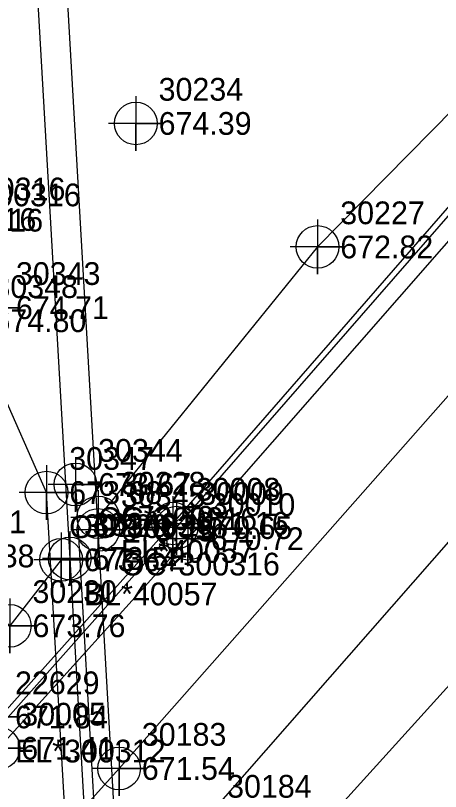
# Model space of a CAD drawing. Extents: x 1331606 to 1438728, y -485208 to 1373898.
# Drawn here: x 1378923.5 to 1378970.2, y 552509.2 to 552594.5 of the extents above; entities that cross this region are included whole.
import ezdxf

# ---------------------------------------------------------------- set-up
doc = ezdxf.new("R2010")
doc.units = 0
for name, color, linetype in [('Exist DTM Breakline', 7, 'Continuous'), ('Exist DTM Breakline Cogo Comment', 7, 'Continuous'), ('Exist DTM Breakline Cogo Elevation', 7, 'Continuous'), ('Exist DTM Breakline Cogo Number', 7, 'Continuous'), ('Exist DTM Breakline Cogo Point CELL', 7, 'Continuous'), ('Exist DTM Crownline', 7, 'Continuous'), ('Exist DTM Crownline Cogo Number', 7, 'Continuous'), ('Exist DTM Drainline', 7, 'Continuous'), ('Exist DTM Drainline Cogo Elevation', 7, 'Continuous'), ('Exist DTM Drainline Cogo Number', 7, 'Continuous'), ('Exist DTM Drainline Cogo Point CELL', 7, 'Continuous'), ('Exist DTM Regular Point CELL', 7, 'Continuous'), ('Exist DTM Regular Point Cogo Elevation', 7, 'Continuous'), ('Exist DTM Regular Point Cogo Number', 7, 'Continuous'), ('Exist Roads Curbs', 7, 'Continuous'), ('Exist Roads Curbs Cogo Elevation', 7, 'Continuous'), ('Exist Roads Curbs Cogo Number', 7, 'Continuous'), ('Exist Roads Curbs Cogo Point CELL', 7, 'Continuous'), ('Exist Roads EOP', 7, 'Continuous'), ('Exist Roads EOP Cogo Elevation', 7, 'Continuous'), ('Exist Roads EOP Cogo Number', 7, 'Continuous'), ('Exist Roads EOP Cogo Point CELL', 7, 'Continuous'), ('Exist Roads EOP Other', 7, 'Continuous'), ('Exist Roads EOP Other Cogo Comment', 7, 'Continuous'), ('Exist Roads EOP Other Cogo Elevation', 7, 'Continuous'), ('Exist Roads EOP Other Cogo Number', 7, 'Continuous'), ('Exist Roads EOP Other Cogo Point CELL', 7, 'Continuous')]:
    doc.layers.add(name, color=color, linetype=linetype)

msp = doc.modelspace()

# ---------------------------------------------------------------- linework, layer by layer
at = {"layer": 'Exist DTM Breakline'}
for points in [[(1378894.8683, 552467.2034), (1378934.875, 552511.6988000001), (1378975.1913, 552557.3482), (1379012.2256, 552601.234), (1379047.8235, 552643.3066), (1379082.4488, 552684.9015), (1379094.3392993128, 552699.1852953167)], [(1378910.6065, 552451.3821), (1378952.3237, 552500.0593), (1378989.7563, 552541.3574), (1379029.1553, 552588.5078000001), (1379065.8772, 552631.0756), (1379101.3476, 552673.4477), (1379110.1890436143, 552683.7234827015)], [(1378951.3861, 552645.2498), (1378973.7368000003, 552623.2363), (1378983.8492, 552608.8693000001), (1378981.7635000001, 552594.4797), (1378956.6937000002, 552569.0235), (1378932.5816, 552539.3052)], [(1378928.5073, 552534.6307), (1378922.8528, 552527.3836), (1378912.8515, 552535.0599), (1378897.7705, 552549.1205)]]:
    msp.add_lwpolyline(points, dxfattribs=at)
at = {"layer": 'Exist DTM Breakline Cogo Point CELL'}
for points in [[(1378956.6937000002, 552572.0235), (1378956.6937000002, 552566.0235), (1378956.6937000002, 552569.0235), (1378959.6937000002, 552569.0235), (1378953.6937000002, 552569.0235)], [(1378932.5816, 552542.3052), (1378932.5816, 552536.3052), (1378932.5816, 552539.3052), (1378935.5816, 552539.3052), (1378929.5816, 552539.3052)], [(1378928.5073, 552537.6307), (1378928.5073, 552531.6307), (1378928.5073, 552534.6307), (1378931.5073, 552534.6307), (1378925.5073, 552534.6307)], [(1378922.8528, 552530.3836), (1378922.8528, 552524.3836), (1378922.8528, 552527.3836), (1378925.8528, 552527.3836), (1378919.8528, 552527.3836)], [(1378934.875, 552514.6988000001), (1378934.875, 552508.6988000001), (1378934.875, 552511.6988000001), (1378937.875, 552511.6988000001), (1378931.875, 552511.6988000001)]]:
    msp.add_lwpolyline(points, dxfattribs=at)
for centre in [(1378956.6937000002, 552569.0235), (1378932.5816, 552539.3052000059), (1378928.5073, 552534.6307000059), (1378922.8528, 552527.3836), (1378934.875, 552511.6988000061)]:
    msp.add_circle(centre, 2.344041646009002, dxfattribs=at)
at = {"layer": 'Exist DTM Crownline'}
msp.add_lwpolyline([(1378902.6769, 552459.2259), (1378944.252, 552505.99), (1378983.1059, 552550.2917), (1379020.4991, 552594.1175), (1379056.3507, 552636.748), (1379092.2886, 552679.84), (1379102.2671428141, 552691.4514903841)], dxfattribs=at)
at = {"layer": 'Exist DTM Drainline'}
msp.add_lwpolyline([(1378909.8591, 552502.9524), (1378941.1956, 552538.1749), (1378973.607, 552575.312), (1378987.747, 552591.8377)], dxfattribs=at)
at = {"layer": 'Exist DTM Drainline Cogo Point CELL'}
msp.add_lwpolyline([(1378941.1956, 552541.1749), (1378941.1956, 552535.1749), (1378941.1956, 552538.1749), (1378944.1956, 552538.1749), (1378938.1956, 552538.1749)], dxfattribs=at)
msp.add_circle((1378941.1956, 552538.1749000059), 2.344041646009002, dxfattribs=at)
at = {"layer": 'Exist DTM Regular Point CELL'}
msp.add_lwpolyline([(1378936.7217, 552585.6003), (1378936.7217, 552579.6003), (1378936.7217, 552582.6003), (1378939.7217, 552582.6003), (1378933.7217, 552582.6003)], dxfattribs=at)
msp.add_circle((1378936.7217, 552582.600300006), 2.344041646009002, dxfattribs=at)
at = {"layer": 'Exist Roads Curbs'}
msp.add_lwpolyline([(1378909.3072, 552503.4156), (1378940.8032, 552538.6427), (1378973.2124, 552575.8521), (1378987.2210000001, 552592.2511)], dxfattribs=at)
at = {"layer": 'Exist Roads Curbs Cogo Point CELL'}
msp.add_lwpolyline([(1378940.8032, 552541.6427), (1378940.8032, 552535.6427), (1378940.8032, 552538.6427), (1378938.0732000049, 552538.6427), (1378943.8032, 552538.6427)], dxfattribs=at)
msp.add_circle((1378940.8032, 552538.6427000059), 2.344041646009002, dxfattribs=at)
at = {"layer": 'Exist Roads EOP'}
msp.add_lwpolyline([(1378887.2676, 552475.3281), (1378921.622, 552513.9192), (1378942.4529, 552536.9515), (1378975.0316, 552574.1483), (1378989.0404, 552590.539)], dxfattribs=at)
msp.add_spline([(1378922.0202, 552447.8495), (1378948.3154, 552477.2189), (1378976.9149, 552509.0975), (1378983.8473, 552517.0012), (1379007.2744000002, 552543.9418), (1379035.5047000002, 552576.1768000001), (1379055.8822, 552599.2135), (1379082.2093, 552631.1586000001), (1379098.0889, 552650.3861)], degree=3, dxfattribs=at)
at = {"layer": 'Exist Roads EOP Cogo Point CELL'}
for points in [[(1378942.4529, 552539.9515), (1378942.4529, 552533.9515), (1378942.4529, 552536.9515), (1378945.4529, 552536.9515), (1378939.4529, 552536.9515)], [(1378921.622, 552516.9192), (1378921.622, 552510.9192), (1378921.622, 552513.9192), (1378924.622, 552513.9192), (1378918.622, 552513.9192)]]:
    msp.add_lwpolyline(points, dxfattribs=at)
for centre in [(1378942.4529, 552536.9515), (1378921.622, 552513.9192)]:
    msp.add_circle(centre, 2.344041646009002, dxfattribs=at)
at = {"layer": 'Exist Roads EOP Other'}
msp.add_line((1378926.8962, 552542.0254000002), (1378918.5576, 552560.9177000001), dxfattribs=at)
msp.add_spline([(1378930.0704, 552542.9155), (1378932.5817, 552537.9158), (1378932.5817, 552537.9158), (1378929.449, 552534.7859), (1378926.8962, 552542.0254000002)], degree=3, dxfattribs=at)
at = {"layer": 'Exist Roads EOP Other Cogo Point CELL'}
for points in [[(1378921.0309, 552565.3498), (1378921.0309, 552559.3498), (1378921.0309, 552562.3498), (1378924.0309, 552562.3498), (1378918.0309, 552562.3498)], [(1378930.0704, 552545.9155), (1378930.0704, 552539.9155), (1378930.0704, 552542.9155), (1378933.0704, 552542.9155), (1378927.0704, 552542.9155)], [(1378926.8962, 552545.0254000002), (1378926.8962, 552539.0254000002), (1378926.8962, 552542.0254000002), (1378929.8962, 552542.0254000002), (1378923.8962, 552542.0254000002)], [(1378932.5817, 552540.9158), (1378932.5817, 552534.9158), (1378932.5817, 552537.9158), (1378935.5817, 552537.9158), (1378929.5817, 552537.9158)], [(1378932.5817000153, 552540.9157999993), (1378932.5817000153, 552534.9157999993), (1378932.5817000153, 552537.9157999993), (1378935.5817000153, 552537.9157999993), (1378929.5817000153, 552537.9157999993)], [(1378929.449, 552537.7859), (1378929.449, 552531.7859), (1378929.449, 552534.7859), (1378932.449, 552534.7859), (1378926.449, 552534.7859)], [(1378920.9316, 552520.3651), (1378920.9316, 552514.3651), (1378920.9316, 552517.3651), (1378923.9316, 552517.3651), (1378917.9316, 552517.3651)]]:
    msp.add_lwpolyline(points, dxfattribs=at)
for centre in [(1378930.0704, 552542.9155), (1378926.8962, 552542.0254000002), (1378932.5817, 552537.9158), (1378932.5817000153, 552537.9157999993), (1378929.449, 552534.785900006)]:
    msp.add_circle(centre, 2.344041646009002, dxfattribs=at)

# ---------------------------------------------------------------- texts
at = {"layer": 'Exist DTM Breakline Cogo Comment'}
for s, p in [('EL*40057', (1378935.0816, 552534.3052)), ('BL*40057', (1378931.0073, 552529.6307))]:
    msp.add_text(s, height=2.5, dxfattribs=at).set_placement(p)
at = {"layer": 'Exist DTM Breakline Cogo Elevation'}
for s, p in [('672.82', (1378959.1937000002, 552567.7735)), ('673.50', (1378935.0816, 552538.0552)), ('674.38', (1378915.3515, 552533.8099)), ('673.64', (1378931.0073, 552533.3807)), ('673.76', (1378925.3528, 552526.1336)), ('671.54', (1378937.375, 552510.4488000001))]:
    msp.add_text(s, height=2.5, dxfattribs=at).set_placement(p)
at = {"layer": 'Exist DTM Breakline Cogo Number'}
for s, p in [('30227', (1378959.1937000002, 552571.5235)), ('30228', (1378935.0816, 552541.8052)), ('30231', (1378915.3515, 552537.5599)), ('30229', (1378931.0073, 552537.1307)), ('30230', (1378925.3528, 552529.8836)), ('30183', (1378937.375, 552514.1988000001))]:
    msp.add_text(s, height=2.5, dxfattribs=at).set_placement(p)
at = {"layer": 'Exist DTM Crownline Cogo Number'}
msp.add_text('30184', height=2.5, dxfattribs=at).set_placement((1378946.752, 552508.49))
at = {"layer": 'Exist DTM Drainline Cogo Elevation'}
msp.add_text('670.65', height=2.5, dxfattribs=at).set_placement((1378943.6956, 552536.9249))
at = {"layer": 'Exist DTM Drainline Cogo Number'}
msp.add_text('30009', height=2.5, dxfattribs=at).set_placement((1378943.6956, 552540.6749))
at = {"layer": 'Exist DTM Regular Point Cogo Elevation'}
msp.add_text('674.39', height=2.5, dxfattribs=at).set_placement((1378939.2217, 552581.3503))
at = {"layer": 'Exist DTM Regular Point Cogo Number'}
msp.add_text('30234', height=2.5, dxfattribs=at).set_placement((1378939.2217, 552585.1003))
at = {"layer": 'Exist Roads Curbs Cogo Elevation'}
msp.add_text('671.16', height=2.5, dxfattribs=at).set_placement((1378943.3032, 552537.3927))
at = {"layer": 'Exist Roads Curbs Cogo Number'}
msp.add_text('30008', height=2.5, dxfattribs=at).set_placement((1378943.3032, 552541.1427))
at = {"layer": 'Exist Roads EOP Cogo Elevation'}
for s, p in [('670.72', (1378944.9529, 552535.7015)), ('671.41', (1378924.122, 552512.6692))]:
    msp.add_text(s, height=2.5, dxfattribs=at).set_placement(p)
at = {"layer": 'Exist Roads EOP Cogo Number'}
for s, p in [('30010', (1378944.9529, 552539.4515)), ('30005', (1378924.122, 552516.4192))]:
    msp.add_text(s, height=2.5, dxfattribs=at).set_placement(p)
at = {"layer": 'Exist Roads EOP Other Cogo Comment'}
for s, p in [('BL*300316', (1378912.43, 552574.1435)), ('OC*300316', (1378913.1886, 552573.4931)), ('OC*300316', (1378909.0551, 552570.7148)), ('CL*300316', (1378909.0443, 552570.7922)), ('OC*300316', (1378932.5704, 552537.9155)), ('OC*300316', (1378929.3962, 552537.0254000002)), ('OC*300316', (1378935.0817, 552532.9158)), ('OC*300316', (1378935.0817, 552532.9158)), ('EL*300312', (1378923.4316, 552512.3651))]:
    msp.add_text(s, height=2.5, dxfattribs=at).set_placement(p)
at = {"layer": 'Exist Roads EOP Other Cogo Elevation'}
for s, p in [('674.71', (1378923.5309, 552561.0998)), ('674.80', (1378921.0576, 552559.6677000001)), ('673.67', (1378932.5704, 552541.6655)), ('673.68', (1378929.3962, 552540.7754000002)), ('673.43', (1378935.0817, 552536.6658)), ('673.43', (1378935.0817, 552536.6658)), ('673.52', (1378931.949, 552533.5359)), ('671.84', (1378923.4316, 552516.1151))]:
    msp.add_text(s, height=2.5, dxfattribs=at).set_placement(p)
at = {"layer": 'Exist Roads EOP Other Cogo Number'}
for s, p in [('30343', (1378923.5309, 552564.8498)), ('30348', (1378921.0576, 552563.4177000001)), ('30344', (1378932.5704, 552545.4155)), ('30347', (1378929.3962, 552544.5254000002)), ('30345', (1378935.0817, 552540.4158)), ('30345', (1378935.0817, 552540.4158)), ('30346', (1378931.949, 552537.2859)), ('22629', (1378923.4316, 552519.8651))]:
    msp.add_text(s, height=2.5, dxfattribs=at).set_placement(p)

doc.saveas('drawing.dxf')
